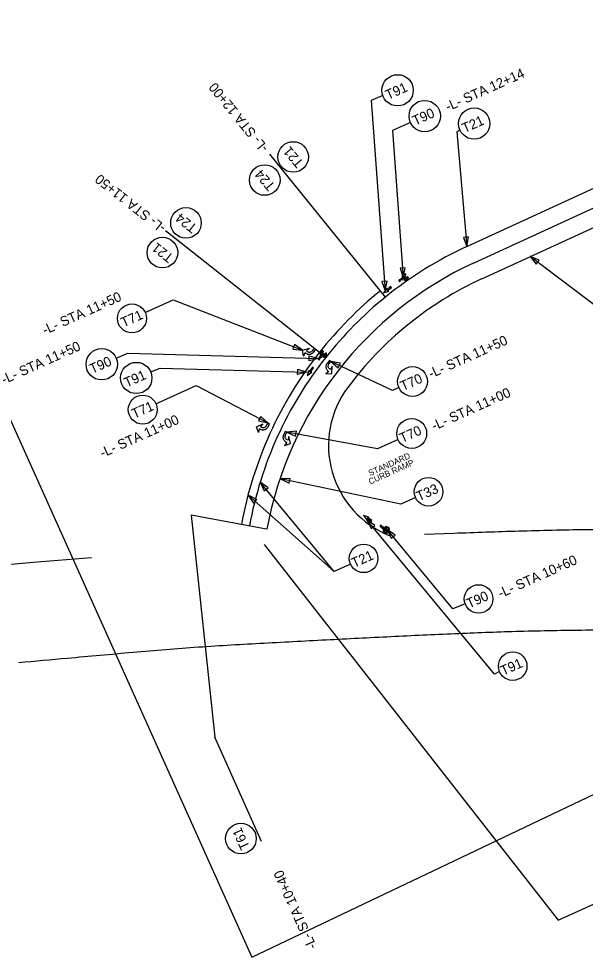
# Model space of a CAD drawing. Extents: x 553958 to 562499, y 493978 to 516388.
# Drawn here: x 554338 to 554688, y 502854 to 503433 of the extents above; entities that cross this region are included whole.
import ezdxf

# ---------------------------------------------------------------- set-up
doc = ezdxf.new("R2010")
doc.units = 0
for name, color, linetype in [('Prop Approach Slab', 7, 'Continuous'), ('Prop Conc 4in Sidewalk', 7, 'Continuous'), ('Prop Dimension', 7, 'Continuous'), ('Prop EOT', 7, 'Continuous'), ('Prop Erosion Rip Rap Class II Label', 7, 'Continuous'), ('Prop Horizontal Alignment Curve and Spiral Data', 7, 'Continuous'), ('Prop Horizontal Alignment Direction Label', 7, 'Continuous'), ('Prop Horizontal Alignment Tick Small', 7, 'Continuous'), ('Prop Roadway Bridge', 7, 'Continuous'), ('Prop SS Fill Line', 7, 'Continuous'), ('Raster_Level_0', 7, 'Continuous'), ('Sheet North Arrow CELL', 7, 'Continuous'), ('Sheet Plan CELL', 7, 'Continuous'), ('Sheet Plot Border Inside CELL', 7, 'Continuous')]:
    doc.layers.add(name, color=color, linetype=linetype)

msp = doc.modelspace()

# ---------------------------------------------------------------- linework, layer by layer
at = {"layer": 'Prop Approach Slab'}
for p, q in [((554564.52, 503261.74), (554493.17, 503349.8)), ((554527.74, 503224.51), (554428.84, 503302.66)), ((554444.77, 503127.07), (554459.24, 502990.11)), ((554489.66, 503109.08), (554671.05, 502877.26)), ((554488.11, 502925.82), (554459.24, 502990.11)), ((554671.05, 502877.26), (554883.52, 502972.67))]:
    msp.add_line(p, q, dxfattribs=at)
at = {"layer": 'Prop Dimension'}
msp.add_line((554380.01, 503108.19), (554380.01, 503108.19), dxfattribs=at)
at = {"layer": 'Prop EOT'}
for radius, start in [(242, 129.01577), (237, 129.01194)]:
    msp.add_arc((554713.7, 503077.59), radius, start, 141.688, dxfattribs=at)
at = {"layer": 'Prop Erosion Rip Rap Class II Label'}
msp.add_lwpolyline([(555793.48, 503466.69), (555600.74, 503885.63), (555438.59, 504238.1), (554125.45, 503648.45), (554482.04, 502854.33), (555335.17, 503260.89)], close=True, dxfattribs=at)
at = {"layer": 'Prop Horizontal Alignment Curve and Spiral Data'}
for points in [[(554530.88, 503222.03), (554530.09, 503222.65), (554528.49, 503220.63), (554528.21, 503220.24), (554528.04, 503219.92), (554527.89, 503219.53), (554527.82, 503219.17), (554527.8, 503218.86), (554527.81, 503218.43), (554527.87, 503218.1), (554527.96, 503217.73), (554528.12, 503217.3), (554528.29, 503217), (554528.54, 503216.64), (554528.95, 503216.21), (554529.58, 503215.71), (554527.66, 503214.37), (554531.49, 503214.63), (554531.58, 503219.03), (554530.57, 503216.96), (554530.05, 503217.37), (554529.77, 503217.62), (554529.55, 503217.91), (554529.42, 503218.17), (554529.28, 503218.55), (554529.21, 503218.84), (554529.21, 503219.27), (554529.3, 503219.68), (554529.42, 503220.07), (554529.68, 503220.53)], [(554530.88, 503222.03), (554530.1, 503222.65), (554528.49, 503220.63), (554528.21, 503220.24), (554528.04, 503219.92), (554527.89, 503219.53), (554527.82, 503219.17), (554527.8, 503218.86), (554527.81, 503218.43), (554527.87, 503218.1), (554527.96, 503217.73), (554528.12, 503217.3), (554528.29, 503217), (554528.55, 503216.64), (554528.95, 503216.21), (554529.58, 503215.71), (554527.66, 503214.37), (554531.49, 503214.63), (554531.58, 503219.03), (554530.57, 503216.96), (554530.05, 503217.37), (554529.77, 503217.62), (554529.56, 503217.91), (554529.42, 503218.17), (554529.28, 503218.55), (554529.21, 503218.84), (554529.21, 503219.27), (554529.3, 503219.68), (554529.42, 503220.07), (554529.69, 503220.53)], [(554503.65, 503178.39), (554502.75, 503178.82), (554501.63, 503176.49), (554501.45, 503176.05), (554501.35, 503175.7), (554501.29, 503175.29), (554501.3, 503174.92), (554501.35, 503174.61), (554501.46, 503174.19), (554501.59, 503173.88), (554501.76, 503173.54), (554502.01, 503173.16), (554502.24, 503172.91), (554502.57, 503172.61), (554503.06, 503172.29), (554503.79, 503171.94), (554502.21, 503170.2), (554505.89, 503171.3), (554505, 503175.61), (554504.48, 503173.37), (554503.87, 503173.66), (554503.55, 503173.84), (554503.28, 503174.07), (554503.09, 503174.3), (554502.87, 503174.64), (554502.73, 503174.91), (554502.64, 503175.32), (554502.63, 503175.75), (554502.67, 503176.15), (554502.82, 503176.66)], [(554503.65, 503178.39), (554502.75, 503178.82), (554501.63, 503176.49), (554501.45, 503176.05), (554501.35, 503175.7), (554501.29, 503175.29), (554501.31, 503174.92), (554501.35, 503174.61), (554501.46, 503174.19), (554501.6, 503173.88), (554501.76, 503173.54), (554502.02, 503173.16), (554502.24, 503172.91), (554502.57, 503172.61), (554503.06, 503172.29), (554503.79, 503171.94), (554502.21, 503170.2), (554505.89, 503171.3), (554505, 503175.61), (554504.48, 503173.37), (554503.88, 503173.66), (554503.55, 503173.84), (554503.28, 503174.07), (554503.09, 503174.3), (554502.87, 503174.64), (554502.73, 503174.91), (554502.64, 503175.32), (554502.63, 503175.75), (554502.67, 503176.15), (554502.82, 503176.66)]]:
    msp.add_lwpolyline(points, close=True, dxfattribs=at)
at = {"layer": 'Prop Horizontal Alignment Direction Label'}
for points in [[(554520.68, 503230.09), (554521.46, 503229.47), (554519.86, 503227.45), (554519.55, 503227.09), (554519.27, 503226.84), (554518.93, 503226.61), (554518.59, 503226.46), (554518.3, 503226.37), (554517.87, 503226.29), (554517.54, 503226.27), (554517.15, 503226.27), (554516.7, 503226.33), (554516.37, 503226.43), (554515.96, 503226.59), (554515.46, 503226.89), (554514.83, 503227.39), (554513.96, 503225.21), (554513.33, 503228.99), (554517.6, 503230.09), (554515.81, 503228.63), (554516.33, 503228.22), (554516.64, 503228), (554516.97, 503227.86), (554517.26, 503227.8), (554517.65, 503227.74), (554517.96, 503227.74), (554518.37, 503227.84), (554518.75, 503228.02), (554519.1, 503228.22), (554519.49, 503228.59)], [(554520.68, 503230.09), (554521.46, 503229.47), (554519.86, 503227.45), (554519.55, 503227.09), (554519.27, 503226.84), (554518.93, 503226.61), (554518.59, 503226.46), (554518.3, 503226.37), (554517.87, 503226.29), (554517.54, 503226.27), (554517.15, 503226.27), (554516.7, 503226.33), (554516.37, 503226.43), (554515.96, 503226.59), (554515.46, 503226.89), (554514.83, 503227.39), (554513.96, 503225.21), (554513.33, 503228.99), (554517.6, 503230.09), (554515.81, 503228.63), (554516.33, 503228.22), (554516.64, 503228), (554516.97, 503227.86), (554517.26, 503227.8), (554517.65, 503227.74), (554517.96, 503227.74), (554518.37, 503227.84), (554518.75, 503228.02), (554519.1, 503228.22), (554519.49, 503228.59)], [(554492.03, 503184.03), (554492.9, 503183.55), (554491.67, 503181.28), (554491.42, 503180.87), (554491.19, 503180.58), (554490.89, 503180.3), (554490.58, 503180.09), (554490.31, 503179.95), (554489.9, 503179.8), (554489.57, 503179.72), (554489.2, 503179.66), (554488.74, 503179.64), (554488.4, 503179.68), (554487.97, 503179.77), (554487.42, 503179.98), (554486.71, 503180.37), (554486.22, 503178.08), (554484.97, 503181.7), (554488.99, 503183.5), (554487.47, 503181.76), (554488.06, 503181.44), (554488.39, 503181.28), (554488.74, 503181.2), (554489.04, 503181.18), (554489.44, 503181.19), (554489.74, 503181.25), (554490.13, 503181.41), (554490.48, 503181.65), (554490.78, 503181.92), (554491.11, 503182.34)], [(554492.03, 503184.03), (554492.9, 503183.55), (554491.67, 503181.28), (554491.42, 503180.87), (554491.19, 503180.58), (554490.89, 503180.3), (554490.58, 503180.09), (554490.31, 503179.95), (554489.9, 503179.8), (554489.57, 503179.72), (554489.2, 503179.66), (554488.74, 503179.64), (554488.4, 503179.68), (554487.97, 503179.77), (554487.42, 503179.98), (554486.71, 503180.37), (554486.22, 503178.08), (554484.97, 503181.7), (554488.99, 503183.5), (554487.47, 503181.76), (554488.06, 503181.44), (554488.39, 503181.28), (554488.74, 503181.2), (554489.04, 503181.18), (554489.44, 503181.19), (554489.74, 503181.25), (554490.13, 503181.41), (554490.48, 503181.65), (554490.78, 503181.92), (554491.11, 503182.34)]]:
    msp.add_lwpolyline(points, close=True, dxfattribs=at)
at = {"layer": 'Prop Horizontal Alignment Tick Small'}
for p, q in [((554575.54, 503275.51), (554575.69, 503275.32)), ((554575.54, 503275.51), (554575.69, 503275.32)), ((554573.07, 503272.26), (554572.98, 503272.38)), ((554573.07, 503272.26), (554572.98, 503272.38)), ((554573.57, 503272.47), (554574.83, 503273.57)), ((554573.84, 503272.28), (554573.57, 503272.47)), ((554573.67, 503271.49), (554573.57, 503271.61)), ((554573.67, 503271.49), (554573.57, 503271.61)), ((554575.18, 503272.19), (554573.84, 503272.28)), ((554574.87, 503273.2), (554574.05, 503272.48)), ((554574.05, 503272.48), (554575.43, 503272.38)), ((554574.83, 503273.57), (554576.84, 503274.23)), ((554575.76, 503272.7), (554574.87, 503273.2)), ((554576.92, 503274.01), (554575.02, 503273.38)), ((554575.02, 503273.38), (554575.7, 503273)), ((554575.43, 503272.38), (554575.18, 503272.19)), ((554575.7, 503273), (554576.12, 503273.49)), ((554576.3, 503273.34), (554575.76, 503272.7)), ((554576.12, 503273.49), (554576.3, 503273.34)), ((554576.19, 503274.67), (554576.34, 503274.48)), ((554576.19, 503274.67), (554576.34, 503274.48)), ((554576.84, 503274.23), (554576.94, 503274.02)), ((554577.03, 503273.58), (554577.18, 503273.38)), ((554577.03, 503273.58), (554577.18, 503273.38)), ((554577.68, 503272.74), (554577.83, 503272.54)), ((554577.68, 503272.74), (554577.83, 503272.54)), ((554523.28, 503223.79), (554523.16, 503223.88)), ((554523.28, 503223.79), (554523.16, 503223.88)), ((554523.7, 503224.15), (554524.59, 503225.56)), ((554524.01, 503224.04), (554523.7, 503224.15)), ((554524.07, 503223.23), (554523.95, 503223.32)), ((554524.07, 503223.23), (554523.95, 503223.32)), ((554525.32, 503224.34), (554524.01, 503224.04)), ((554524.74, 503225.21), (554524.15, 503224.29)), ((554524.15, 503224.29), (554525.5, 503224.59)), ((554524.59, 503225.56), (554526.32, 503226.77)), ((554524.7, 503227.62), (554524.9, 503227.48)), ((554524.7, 503227.62), (554524.9, 503227.48)), ((554525.72, 503224.99), (554524.74, 503225.21)), ((554526.46, 503226.58), (554524.83, 503225.44)), ((554524.83, 503225.44), (554525.58, 503225.26)), ((554525.5, 503224.59), (554525.32, 503224.34)), ((554525.57, 503227.01), (554525.76, 503226.86)), ((554525.57, 503227.01), (554525.76, 503226.86)), ((554525.58, 503225.26), (554525.84, 503225.86)), ((554526.06, 503225.76), (554525.72, 503224.99)), ((554525.84, 503225.86), (554526.06, 503225.76)), ((554526.32, 503226.77), (554526.48, 503226.6)), ((554526.69, 503226.2), (554526.89, 503226.06)), ((554526.69, 503226.2), (554526.89, 503226.06)), ((554527.55, 503225.58), (554527.75, 503225.44)), ((554527.55, 503225.58), (554527.75, 503225.44)), ((554561.51, 503119.83), (554561.58, 503119.96)), ((554561.51, 503119.83), (554561.58, 503119.96)), ((554561.99, 503120.68), (554562.06, 503120.81)), ((554561.99, 503120.68), (554562.06, 503120.81)), ((554562.31, 503119.98), (554562.38, 503120.3)), ((554562.74, 503118.71), (554562.31, 503119.98)), ((554562.38, 503120.3), (554563.88, 503119.56)), ((554563.55, 503119.38), (554562.57, 503119.86)), ((554562.57, 503119.86), (554563.01, 503118.55)), ((554563.01, 503118.55), (554562.74, 503118.71)), ((554563.43, 503118.37), (554563.55, 503119.38)), ((554564.24, 503118.12), (554563.43, 503118.37)), ((554563.78, 503119.32), (554563.69, 503118.54)), ((554563.69, 503118.54), (554564.31, 503118.35)), ((554565.09, 503117.81), (554563.78, 503119.32)), ((554563.88, 503119.56), (554565.27, 503117.97)), ((554564.31, 503118.35), (554564.24, 503118.12)), ((554565.42, 503118.74), (554565.3, 503118.53)), ((554565.42, 503118.74), (554565.3, 503118.53)), ((554565.94, 503119.67), (554565.82, 503119.45)), ((554565.94, 503119.67), (554565.82, 503119.45)), ((554564.21, 503116.62), (554564.09, 503116.4)), ((554564.21, 503116.62), (554564.09, 503116.4)), ((554564.74, 503117.54), (554564.62, 503117.33)), ((554564.74, 503117.54), (554564.62, 503117.33)), ((554565.27, 503117.97), (554565.11, 503117.79))]:
    msp.add_line(p, q, dxfattribs=at)
for points in [[(554566.56, 503265.43), (554565.63, 503265.59), (554568.32, 503267.67), (554567.93, 503268.17), (554565.24, 503266.1), (554565.33, 503267.03), (554563.38, 503264.25)], [(554566.56, 503265.43), (554565.63, 503265.59), (554568.32, 503267.67), (554567.93, 503268.17), (554565.24, 503266.1), (554565.33, 503267.03), (554563.38, 503264.25)], [(554519.01, 503215.38), (554518.08, 503215.27), (554520.06, 503218.03), (554519.54, 503218.4), (554517.56, 503215.64), (554517.37, 503216.56), (554516.31, 503213.34)], [(554519.01, 503215.38), (554518.08, 503215.27), (554520.06, 503218.03), (554519.54, 503218.4), (554517.56, 503215.64), (554517.37, 503216.56), (554516.31, 503213.34)], [(554553.12, 503124.33), (554553, 503125.26), (554555.78, 503123.32), (554556.15, 503123.84), (554553.36, 503125.78), (554554.28, 503125.99), (554551.04, 503127.01)], [(554553.12, 503124.33), (554553, 503125.26), (554555.78, 503123.32), (554556.15, 503123.84), (554553.36, 503125.78), (554554.28, 503125.99), (554551.04, 503127.01)]]:
    msp.add_lwpolyline(points, close=True, dxfattribs=at)
for centre, radius, start, end in [((554573.32, 503271.93), 0.563, 127.66921, 307.66921), ((554573.32, 503271.93), 0.563, 127.66921, 307.66921), ((554573.32, 503271.93), 0.41, 307.66921, 127.66921), ((554523.62, 503223.55), 0.563, 144.42034, 324.42034), ((554523.62, 503223.55), 0.563, 144.42034, 324.42034), ((554523.62, 503223.55), 0.41, 324.42034, 144.42034), ((554561.78, 503120.32), 0.563, 60.47699, 240.47699), ((554561.78, 503120.32), 0.563, 60.47699, 240.47699), ((554561.78, 503120.32), 0.41, 240.47699, 60.47699)]:
    msp.add_arc(centre, radius, start, end, dxfattribs=at)
for centre, major_axis, ratio, start_param, end_param in [((554575.94, 503275), (1.18, 0.91), 0.435841, 1.570796, 4.712389), ((554575.94, 503275), (0.99, 0.765), 0.325967, 1.570796, 4.712389), ((554575.94, 503275), (1.18, 0.91), 0.435841, 4.712389, 7.853982), ((554575.94, 503275), (0.99, 0.765), 0.325967, 4.712389, 7.853982), ((554577.43, 503273.06), (1.18, 0.91), 0.435841, 1.570796, 4.712389), ((554577.43, 503273.06), (0.99, 0.765), 0.325967, 1.570796, 4.712389), ((554577.43, 503273.06), (1.18, 0.91), 0.435841, 4.712389, 7.853982), ((554577.43, 503273.06), (0.99, 0.765), 0.325967, 4.712389, 7.853982), ((554525.23, 503227.24), (0.87, 1.22), 0.435841, 4.712389, 7.853982), ((554525.23, 503227.24), (0.87, 1.22), 0.435841, 1.570796, 4.712389), ((554525.23, 503227.24), (0.73, 1.02), 0.325967, 1.570796, 4.712389), ((554525.23, 503227.24), (0.73, 1.02), 0.325967, 4.712389, 7.853982), ((554527.22, 503225.82), (0.87, 1.22), 0.435841, 1.570796, 4.712389), ((554527.22, 503225.82), (0.73, 1.02), 0.325967, 1.570796, 4.712389), ((554527.22, 503225.82), (0.87, 1.22), 0.435841, 4.712389, 7.853982), ((554527.22, 503225.82), (0.73, 1.02), 0.325967, 4.712389, 7.853982), ((554565.62, 503119.1), (1.3, -0.74), 0.435841, 1.570796, 4.712389), ((554565.62, 503119.1), (1.09, -0.62), 0.325967, 1.570796, 4.712389), ((554565.62, 503119.1), (1.3, -0.74), 0.435841, 4.712389, 7.853982), ((554565.62, 503119.1), (1.09, -0.62), 0.325967, 4.712389, 7.853982), ((554564.42, 503116.97), (1.3, -0.74), 0.435841, 1.570796, 4.712389), ((554564.42, 503116.97), (1.09, -0.62), 0.325967, 1.570796, 4.712389), ((554564.42, 503116.97), (1.3, -0.74), 0.435841, 4.712389, 7.853982), ((554564.42, 503116.97), (1.09, -0.62), 0.325967, 4.712389, 7.853982)]:
    msp.add_ellipse(centre, major_axis=major_axis, ratio=ratio, start_param=start_param, end_param=end_param, dxfattribs=at)
at = {"layer": 'Prop Roadway Bridge'}
msp.add_line((554606.63, 503115.85), (554588.67, 503115.16), dxfattribs=at)
msp.add_lwpolyline([(554383.28, 503100.9), (554347.29, 503097.97), (554321.89, 503095.7)], dxfattribs=at)
for points in [[(555009.62, 503103.27), (554970.38, 503107.1), (554930.52, 503110.3), (554891.2, 503112.58), (554850.59, 503114.56), (554809.97, 503115.97), (554768.8, 503117.22), (554729.86, 503117.84), (554688.09, 503118.07), (554646.73, 503117.18), (554606.63, 503115.85)], [(555002.05, 503041.83), (554964.24, 503045.65), (554925.55, 503048.89), (554886.08, 503051.15), (554847.29, 503053.26), (554810.28, 503054.49), (554766.79, 503055.75), (554727.94, 503056.26), (554687.99, 503056.08), (554647.36, 503055.32), (554609.74, 503053.99), (554570.3, 503052.17), (554530.42, 503050.16), (554489.62, 503048), (554449.13, 503045.57), (554408.82, 503042.34), (554368.28, 503038.73), (554338.38, 503036.05)]]:
    msp.add_spline(points, degree=3, dxfattribs=at)
at = {"layer": 'Prop SS Fill Line'}
msp.add_line((554383.28, 503100.9), (554383.28, 503100.9), dxfattribs=at)
at = {"layer": 'Raster_Level_0'}
msp.add_line((554619.25, 503282.9), (555064.66, 503487.54), dxfattribs=at)
msp.add_arc((554713.7, 503077.59), 226, 114.70456, 169.57533, dxfattribs=at)
at = {"layer": 'Sheet North Arrow CELL'}
msp.add_line((554491.19, 503118.53), (554444.77, 503127.07), dxfattribs=at)
at = {"layer": 'Sheet Plan CELL'}
for points in [[(554562.92, 503386.09), (554555.75, 503383.02), (554564.35, 503265.64)], [(554579.92, 503369.46), (554568.82, 503364.47), (554575.47, 503273.78)], [(554610.48, 503364.69), (554608.47, 503363.76), (554614.65, 503292.9)], [(554709.8, 503257.22), (554699.11, 503252.42), (554653.77, 503286.66)], [(554416.34, 503252.23), (554433.5, 503259.93), (554513.33, 503228.99)], [(554398.47, 503223.94), (554405.63, 503227.04), (554523.28, 503223.79)], [(554419.76, 503215.48), (554425.57, 503217.93), (554516.17, 503215.42)], [(554572.79, 503205.84), (554568.77, 503204.03), (554530.88, 503222.03)], [(554422.98, 503195.9), (554447.83, 503207.06), (554492.03, 503184.03)], [(554572.3, 503173.74), (554559.68, 503168.08), (554503.65, 503178.39)], [(554542.98, 503096.86), (554532.82, 503092.3), (554487.26, 503147.53)], [(554583.02, 503137.96), (554574.04, 503133.93), (554499.72, 503149.51)], [(554542.98, 503096.86), (554532.82, 503092.3), (554479.76, 503139.5)], [(554634.77, 503030.6), (554631.74, 503029.02), (554553.12, 503124.33)], [(554613.66, 503072.39), (554606.12, 503069.28), (554565.63, 503118.37)]]:
    msp.add_lwpolyline(points, dxfattribs=at)
for points in [[(554612.57, 503298.52), (554614.65, 503292.9), (554615.67, 503298.81)], [(554659.33, 503284.4), (554653.77, 503286.66), (554657.46, 503281.92)], [(554573.49, 503279.45), (554575.47, 503273.78), (554576.59, 503279.67)], [(554562.38, 503271.31), (554564.35, 503265.64), (554565.48, 503271.54)], [(554507.37, 503229.64), (554513.33, 503228.99), (554508.49, 503232.54)], [(554517.53, 503225.51), (554523.28, 503223.79), (554517.45, 503222.4)], [(554510.42, 503217.14), (554516.17, 503215.42), (554510.33, 503214.03)], [(554536.78, 503220.95), (554530.88, 503222.03), (554535.45, 503218.14)], [(554486.17, 503185.33), (554492.03, 503184.03), (554487.6, 503188.08)], [(554509.63, 503178.87), (554503.65, 503178.39), (554509.07, 503175.81)], [(554492.15, 503144.05), (554487.26, 503147.53), (554489.75, 503142.07)], [(554505.71, 503149.84), (554499.72, 503149.51), (554505.07, 503146.8)], [(554485.12, 503136.81), (554479.76, 503139.5), (554483.06, 503134.49)], [(554558.01, 503120.85), (554553.12, 503124.33), (554555.61, 503118.87)], [(554570.52, 503114.88), (554565.63, 503118.37), (554568.12, 503112.91)]]:
    msp.add_lwpolyline(points, close=True, dxfattribs=at)
for centre, radius in [((554572.03, 503389.3), 9.66), ((554588.73, 503373.41), 9.66), ((554619.23, 503368.77), 9.66), ((554507.6, 503348.17), 9.44), ((554490.04, 503333.95), 9.44), ((554441.5, 503307.45), 9.44), ((554426.94, 503289.17), 9.44), ((554408.19, 503248.56), 8.94), ((554389.55, 503220.23), 9.66), ((554410.84, 503211.78), 9.66), ((554581.2, 503209.61), 9.22), ((554414.82, 503192.24), 8.94), ((554580.7, 503177.52), 9.22), ((554591.07, 503141.57), 8.82), ((554551.03, 503100.47), 8.82), ((554621.95, 503075.41), 8.82), ((554642.98, 503033.95), 8.82), ((554475.37, 502927.53), 9.44)]:
    msp.add_circle(centre, radius, dxfattribs=at)
at = {"layer": 'Sheet Plot Border Inside CELL'}
for p, q in [((554614.65, 503292.9), (555559.74, 503727.68)), ((554623.85, 503272.91), (555048.71, 503468.37)), ((554383.28, 503100.9), (554383.28, 503100.9))]:
    msp.add_line(p, q, dxfattribs=at)
for centre, radius, start, end in [((554713.7, 503077.59), 237, 114.70456, 129.01194), ((554713.7, 503077.59), 215, 114.70456, 143.32746), ((554713.7, 503077.59), 242, 141.688, 169.57533), ((554713.7, 503077.59), 237, 141.688, 169.57533), ((554589.38, 503170.16), 60, 143.32746, 248.2667)]:
    msp.add_arc(centre, radius, start, end, dxfattribs=at)

# ---------------------------------------------------------------- texts
at = {"layer": 'Prop Conc 4in Sidewalk'}
for s, p in [('STANDARD ', (554555.04, 503151.15)), ('CURB RAMP', (554555.06, 503145.94))]:
    msp.add_text(s, height=3.75, rotation=24.18158, dxfattribs=at).set_placement(p)
at = {"layer": 'Sheet Plan CELL'}
for s, rotation, p in [('-L- STA 12+14', 24.18158, (554603.09, 503376.21)), ('-L- STA 12+00', 129.01194, (554492.69, 503353.95)), ('T91', 24.17847, (554566.12, 503383.36)), ('T90', 24.17847, (554582.81, 503367.47)), ('T21', 24.17847, (554613.32, 503362.83)), ('T21', 130.29836, (554514.46, 503344.71)), ('T24', 130.29836, (554496.91, 503330.5)), ('-L- STA 11+50', 141.688, (554429.58, 503305.47)), ('T24', 141.80969, (554448.92, 503305.43)), ('T21', 141.80969, (554434.36, 503287.15)), ('-L- STA 11+50', 24.18158, (554354.51, 503238.33)), ('T71', 24.18158, (554402.96, 503242.93)), ('-L- STA 11+50', 24.18158, (554329.26, 503207.79)), ('-L- STA 11+50', 24.18158, (554592.63, 503211.43)), ('T90', 24.17847, (554383.64, 503214.29)), ('T91', 24.17847, (554404.93, 503205.83)), ('T70', 24.18158, (554575.29, 503203.67)), ('-L- STA 11+00', 24.18158, (554594.53, 503179.18)), ('T71', 24.18158, (554409.59, 503186.6)), ('-L- STA 11+00', 24.18158, (554390.01, 503162.46)), ('T70', 24.18158, (554574.79, 503171.57)), ('T33', 24.18158, (554585.18, 503135.64)), ('T21', 24.18158, (554545.15, 503094.54)), ('-L- STA 10+60', 24.18158, (554635.5, 503075.88)), ('T90', 24.18158, (554616.07, 503069.48)), ('T91', 24.18158, (554637.09, 503028.02)), ('T61', 114.18158, (554481.01, 502922.3)), ('-L- STA 10+40', 114.18158, (554522.27, 502860.87))]:
    msp.add_text(s, height=6, rotation=rotation, dxfattribs=at).set_placement(p)

doc.saveas('drawing.dxf')
